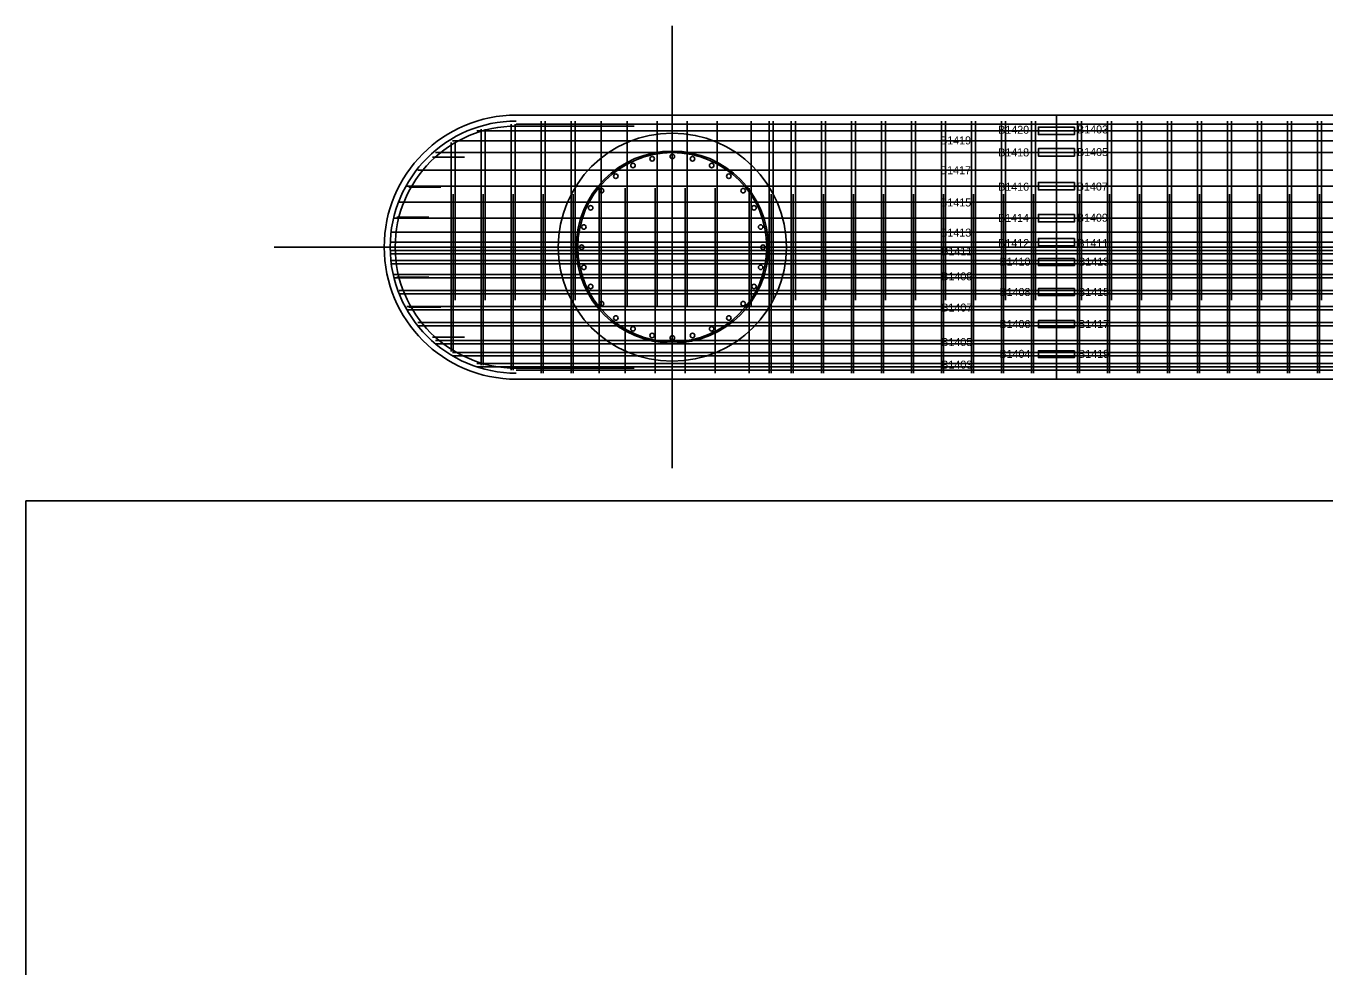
# Model space of a CAD drawing. Extents: x 653466 to 653585, y 408325 to 408579.
# Drawn here: x 653466 to 653520, y 408370 to 408409.1 of the extents above; entities that cross this region are included whole.
import ezdxf

# ---------------------------------------------------------------- set-up
doc = ezdxf.new("R2010")
doc.units = 0
for name, color, linetype in [('B_Boring', 7, 'Continuous'), ('B_Boring Annot', 7, 'Continuous'), ('BD-PROP-OSB', 7, 'Continuous'), ('R_Border_Divider', 7, 'Continuous'), ('R_Proposed Const Limits Fill', 7, 'Continuous'), ('R_Shade By Others', 7, 'Continuous'), ('R_Shade Removal', 7, 'Continuous'), ('R_Survey Control', 7, 'Continuous'), ('R_Wall', 7, 'Continuous')]:
    doc.layers.add(name, color=color, linetype=linetype)

msp = doc.modelspace()

# ---------------------------------------------------------------- linework, layer by layer
at = {"layer": 'B_Boring'}
msp.add_line((653571.459, 408399.933), (653476.296, 408399.933), dxfattribs=at)
at = {"layer": 'B_Boring Annot'}
msp.add_circle((653492.878, 408399.933), 4.75, dxfattribs=at)
at = {"layer": 'BD-PROP-OSB'}
for p, q in [((653499.086, 408405.183), (653499.086, 408394.683)), ((653499.253, 408405.183), (653499.253, 408397.725)), ((653500.336, 408405.183), (653500.336, 408394.683)), ((653500.503, 408405.183), (653500.503, 408397.725)), ((653501.586, 408405.183), (653501.586, 408394.683)), ((653501.753, 408405.183), (653501.753, 408397.725)), ((653502.836, 408405.183), (653502.836, 408394.683)), ((653503.003, 408405.183), (653503.003, 408397.725)), ((653504.086, 408405.183), (653504.086, 408394.683)), ((653504.253, 408405.183), (653504.253, 408397.725)), ((653505.336, 408405.183), (653505.336, 408394.683)), ((653505.503, 408405.183), (653505.503, 408397.725)), ((653506.586, 408405.183), (653506.586, 408394.683)), ((653506.753, 408405.183), (653506.753, 408397.725)), ((653511.003, 408405.183), (653511.003, 408394.683)), ((653511.169, 408405.183), (653511.169, 408397.725)), ((653512.253, 408405.183), (653512.253, 408394.683)), ((653512.419, 408405.183), (653512.419, 408397.725)), ((653513.503, 408405.183), (653513.503, 408394.683)), ((653513.669, 408405.183), (653513.669, 408397.725)), ((653514.753, 408405.183), (653514.753, 408394.683)), ((653514.919, 408405.183), (653514.919, 408397.725)), ((653516.003, 408405.183), (653516.003, 408394.683)), ((653516.169, 408405.183), (653516.169, 408397.725)), ((653517.253, 408405.183), (653517.253, 408394.683)), ((653517.419, 408405.183), (653517.419, 408397.725)), ((653518.503, 408405.183), (653518.503, 408394.683)), ((653518.669, 408405.183), (653518.669, 408397.725)), ((653499.169, 408402.141), (653499.169, 408394.683)), ((653500.419, 408402.141), (653500.419, 408394.683)), ((653501.669, 408402.141), (653501.669, 408394.683)), ((653502.919, 408402.141), (653502.919, 408394.683)), ((653504.169, 408402.141), (653504.169, 408394.683)), ((653505.419, 408402.141), (653505.419, 408394.683)), ((653506.669, 408402.141), (653506.669, 408394.683)), ((653511.086, 408402.141), (653511.086, 408394.683)), ((653512.336, 408402.141), (653512.336, 408394.683)), ((653513.586, 408402.141), (653513.586, 408394.683)), ((653514.836, 408402.141), (653514.836, 408394.683)), ((653516.086, 408402.141), (653516.086, 408394.683)), ((653517.336, 408402.141), (653517.336, 408394.683)), ((653518.586, 408402.141), (653518.586, 408394.683))]:
    msp.add_line(p, q, dxfattribs=at)
at = {"layer": 'R_Border_Divider'}
msp.add_line((653508.878, 408405.433), (653508.878, 408394.433), dxfattribs=at)
at = {"layer": 'R_Proposed Const Limits Fill'}
for p, q in [((653486.169, 408405.054), (653486.169, 408394.812)), ((653486.336, 408405.054), (653486.336, 408397.725)), ((653486.378, 408405.058), (653563.378, 408405.058)), ((653486.378, 408404.975), (653491.295, 408404.975)), ((653487.419, 408405.183), (653487.419, 408394.683)), ((653487.586, 408405.183), (653487.586, 408397.725)), ((653488.669, 408405.183), (653488.669, 408394.683)), ((653488.836, 408405.183), (653488.836, 408397.725)), ((653489.92, 408405.183), (653489.92, 408397.475)), ((653491.003, 408405.183), (653491.003, 408397.475)), ((653492.253, 408405.183), (653492.253, 408397.475)), ((653493.503, 408405.183), (653493.503, 408397.475)), ((653494.753, 408405.183), (653494.753, 408397.475)), ((653496.17, 408405.183), (653496.17, 408397.475)), ((653496.919, 408405.183), (653496.919, 408394.683)), ((653497.086, 408405.183), (653497.086, 408397.725)), ((653497.836, 408405.183), (653497.836, 408394.683)), ((653498.003, 408405.183), (653498.003, 408397.725)), ((653507.836, 408405.183), (653507.836, 408394.683)), ((653508.003, 408405.183), (653508.003, 408397.725)), ((653509.753, 408405.183), (653509.753, 408394.683)), ((653509.919, 408405.183), (653509.919, 408397.725)), ((653519.753, 408405.183), (653519.753, 408394.683)), ((653519.919, 408405.183), (653519.919, 408397.725)), ((653483.722, 408404.362), (653540.878, 408404.362)), ((653484.738, 408404.779), (653508.878, 408404.779)), ((653484.919, 408404.846), (653484.919, 408395.02)), ((653485.086, 408404.846), (653485.086, 408397.725)), ((653508.878, 408404.779), (653565.018, 408404.779)), ((653483.012, 408403.881), (653508.878, 408403.881)), ((653483.669, 408404.284), (653483.669, 408395.582)), ((653483.836, 408404.284), (653483.836, 408397.725)), ((653508.878, 408403.881), (653566.744, 408403.881)), ((653482.885, 408403.683), (653484.218, 408403.683)), ((653482.278, 408403.141), (653540.878, 408403.141)), ((653481.824, 408402.475), (653508.878, 408402.475)), ((653481.904, 408402.433), (653483.237, 408402.433)), ((653489.836, 408402.391), (653489.836, 408394.683)), ((653490.92, 408402.391), (653490.92, 408394.683)), ((653492.17, 408402.391), (653492.17, 408394.683)), ((653493.42, 408402.391), (653493.42, 408394.683)), ((653494.67, 408402.391), (653494.67, 408394.683)), ((653496.086, 408402.391), (653496.086, 408394.683)), ((653508.878, 408402.475), (653567.932, 408402.475)), ((653481.502, 408401.808), (653540.878, 408401.808)), ((653483.753, 408402.141), (653483.753, 408395.582)), ((653485.003, 408402.141), (653485.003, 408395.02)), ((653486.253, 408402.141), (653486.253, 408394.812)), ((653487.503, 408402.141), (653487.503, 408394.683)), ((653488.753, 408402.141), (653488.753, 408394.683)), ((653497.003, 408402.141), (653497.003, 408394.683)), ((653497.919, 408402.141), (653497.919, 408394.683)), ((653507.919, 408402.141), (653507.919, 408394.683)), ((653509.836, 408402.141), (653509.836, 408394.683)), ((653519.836, 408402.141), (653519.836, 408394.683)), ((653481.286, 408401.141), (653508.878, 408401.141)), ((653481.408, 408401.183), (653482.741, 408401.183)), ((653508.878, 408401.141), (653568.47, 408401.141)), ((653481.174, 408400.558), (653540.878, 408400.558)), ((653481.132, 408400.141), (653508.878, 408400.141)), ((653508.878, 408400.141), (653568.62, 408400.141)), ((653481.132, 408399.795), (653540.878, 408399.795)), ((653481.132, 408399.654), (653540.878, 408399.654)), ((653481.253, 408399.933), (653482.586, 408399.933)), ((653481.174, 408399.378), (653508.878, 408399.378)), ((653481.174, 408399.237), (653508.878, 408399.237)), ((653508.878, 408399.378), (653568.582, 408399.378)), ((653508.878, 408399.237), (653568.582, 408399.237)), ((653481.286, 408398.795), (653540.878, 408398.795)), ((653481.286, 408398.654), (653540.878, 408398.654)), ((653481.408, 408398.683), (653482.741, 408398.683)), ((653481.502, 408398.128), (653508.878, 408398.128)), ((653481.502, 408397.987), (653508.878, 408397.987)), ((653508.878, 408398.128), (653568.254, 408398.128)), ((653508.878, 408397.987), (653568.254, 408397.987)), ((653481.824, 408397.462), (653540.878, 408397.462)), ((653481.824, 408397.321), (653540.878, 408397.321)), ((653481.904, 408397.433), (653483.237, 408397.433)), ((653482.278, 408396.795), (653508.878, 408396.795)), ((653508.878, 408396.795), (653567.478, 408396.795)), ((653482.278, 408396.654), (653508.878, 408396.654)), ((653508.878, 408396.654), (653567.478, 408396.654)), ((653482.885, 408396.183), (653484.218, 408396.183)), ((653483.012, 408396.045), (653540.878, 408396.045)), ((653483.012, 408395.904), (653540.878, 408395.904)), ((653483.722, 408395.545), (653508.878, 408395.545)), ((653483.722, 408395.404), (653508.878, 408395.404)), ((653508.878, 408395.545), (653566.033, 408395.545)), ((653508.878, 408395.404), (653566.033, 408395.404)), ((653484.738, 408395.087), (653540.878, 408395.087)), ((653484.738, 408394.946), (653540.878, 408394.946)), ((653486.378, 408394.891), (653491.295, 408394.891)), ((653486.378, 408394.808), (653563.378, 408394.808))]:
    msp.add_line(p, q, dxfattribs=at)
for points in [[(653509.628, 408404.935), (653508.128, 408404.935), (653508.128, 408404.623), (653509.628, 408404.623)], [(653509.628, 408404.037), (653508.128, 408404.037), (653508.128, 408403.725), (653509.628, 408403.725)], [(653509.628, 408402.631), (653508.128, 408402.631), (653508.128, 408402.318), (653509.628, 408402.318)], [(653509.628, 408401.297), (653508.128, 408401.297), (653508.128, 408400.985), (653509.628, 408400.985)], [(653509.628, 408400.297), (653508.128, 408400.297), (653508.128, 408399.985), (653509.628, 408399.985)], [(653509.628, 408399.454), (653508.128, 408399.454), (653508.128, 408399.162), (653509.628, 408399.162)], [(653509.628, 408398.204), (653508.128, 408398.204), (653508.128, 408397.912), (653509.628, 408397.912)], [(653509.628, 408396.87), (653508.128, 408396.87), (653508.128, 408396.579), (653509.628, 408396.579)], [(653509.628, 408395.62), (653508.128, 408395.62), (653508.128, 408395.329), (653509.628, 408395.329)]]:
    msp.add_lwpolyline(points, close=True, dxfattribs=at)
for centre, radius in [((653492.878, 408399.933), 4), ((653492.878, 408399.933), 3.937), ((653492.878, 408403.709), 0.094), ((653491.24, 408403.335), 0.094), ((653492.038, 408403.614), 0.094), ((653493.718, 408403.614), 0.094), ((653494.516, 408403.335), 0.094), ((653490.524, 408402.885), 0.094), ((653495.232, 408402.885), 0.094), ((653489.926, 408402.287), 0.094), ((653495.83, 408402.287), 0.094), ((653489.476, 408401.571), 0.094), ((653496.28, 408401.571), 0.094), ((653489.197, 408400.773), 0.094), ((653496.559, 408400.773), 0.094), ((653489.102, 408399.933), 0.094), ((653496.654, 408399.933), 0.094), ((653489.197, 408399.093), 0.094), ((653496.559, 408399.093), 0.094), ((653489.476, 408398.295), 0.094), ((653496.28, 408398.295), 0.094), ((653489.926, 408397.579), 0.094), ((653495.83, 408397.579), 0.094), ((653490.524, 408396.981), 0.094), ((653495.232, 408396.981), 0.094), ((653491.24, 408396.531), 0.094), ((653492.038, 408396.252), 0.094), ((653492.878, 408396.157), 0.094), ((653493.718, 408396.252), 0.094), ((653494.516, 408396.531), 0.094)]:
    msp.add_circle(centre, radius, dxfattribs=at)
for start, end in [(90, 180), (180, 270)]:
    msp.add_arc((653486.378, 408399.933), 5.042, start, end, dxfattribs=at)
at = {"layer": 'R_Shade By Others'}
msp.add_lwpolyline([(653465.958, 408389.369), (653581.187, 408389.369), (653581.187, 408336.489), (653465.958, 408336.489)], close=True, dxfattribs=at)
at = {"layer": 'R_Shade Removal'}
for p, q in [((653486.376, 408405.433), (653563.378, 408405.433)), ((653486.378, 408394.433), (653563.378, 408394.433))]:
    msp.add_line(p, q, dxfattribs=at)
for radius in [5.5, 5.25]:
    msp.add_arc((653486.378, 408399.933), radius, 90.0159, 270, dxfattribs=at)
at = {"layer": 'R_Wall'}
msp.add_line((653492.878, 408390.721), (653492.878, 408409.145), dxfattribs=at)

# ---------------------------------------------------------------- texts
at = {"layer": 'R_Survey Control'}
for s, p in [('B1420', (653506.452, 408404.654)), ('B1403', (653509.739, 408404.668)), ('B1419', (653504.032, 408404.211)), ('B1418', (653506.45, 408403.712)), ('B1405', (653509.736, 408403.726)), ('B1417', (653504.03, 408402.97)), ('B1416', (653506.449, 408402.283)), ('B1407', (653509.729, 408402.29)), ('B1415', (653504.037, 408401.626)), ('B1414', (653506.445, 408400.984)), ('B1409', (653509.731, 408400.991)), ('B1413', (653504.039, 408400.371)), ('B1412', (653506.454, 408399.935)), ('B1411', (653509.75, 408399.935)), ('B1411', (653504.083, 408399.598)), ('B1410', (653506.504, 408399.161)), ('B1413', (653509.783, 408399.161)), ('B1409', (653504.083, 408398.549)), ('B1408', (653506.504, 408397.899)), ('B1415', (653509.783, 408397.899)), ('B1407', (653504.083, 408397.25)), ('B1406', (653506.504, 408396.563)), ('B1417', (653509.783, 408396.563)), ('B1405', (653504.083, 408395.813)), ('B1403', (653504.083, 408394.872)), ('B1404', (653506.504, 408395.321)), ('B1419', (653509.783, 408395.321))]:
    msp.add_text(s, height=0.3333, dxfattribs=at).set_placement(p)

doc.saveas('drawing.dxf')
